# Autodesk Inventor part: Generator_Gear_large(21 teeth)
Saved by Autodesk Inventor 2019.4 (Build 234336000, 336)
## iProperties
Created: 2020-04
Part Number: Generator_Gear_large(21 teeth)
Material: Generic
Description: Spur Gear; Module: 0.900000; Num Teeth: 21; Pressure Angle: 20.000000; Backlash: 0.00 mm
Document SubType Name: Modeling
Designer: Administrator
Density: 1 g/cm^3
Appearance: Default
Title: Generator_Gear_large(21 teeth) v5
Author: Administrator
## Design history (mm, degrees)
feature "Body1"
body "Solid1"
